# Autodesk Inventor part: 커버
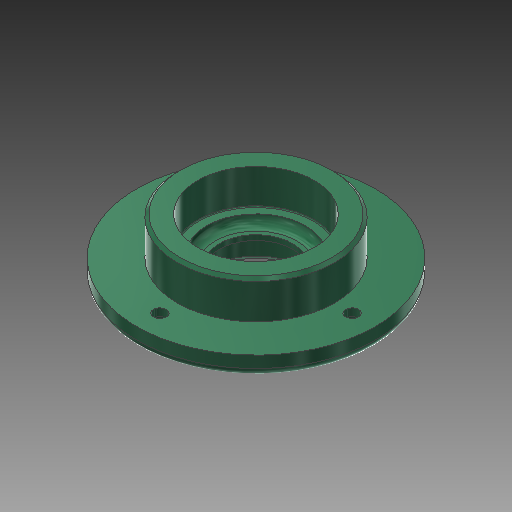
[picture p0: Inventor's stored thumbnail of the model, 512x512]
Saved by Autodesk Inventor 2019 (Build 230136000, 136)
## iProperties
Company: 한국ATC센터
Created: 2014-10
Part Number: 커버
Document SubType Name: Modeling
Designer: KYOUNG IL JANG
Density: 2.71 g/cm^3
Mass: 121.214 g
Surface Area: 161.165 cm^2
Volume: 44.7286 cm^3
Material: 알루미늄 6061
Appearance: 알루미늄 - 평지
Author: KYOUNG IL JANG
Revision Number: 1
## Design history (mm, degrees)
sketch "스케치1"
  geometry: C1 r 41 at (0, 0); 1 further point
  constraints: 1 centre point, 1 coincident
  dimensions: "d0" = 82 diameter of C1
extrude "돌출1" new body sketch "스케치1" distance "d1" = 7; taper "d2" = 0 deg
sketch "스케치2"
  geometry: C1 r 27 at (0, 0); 1 further point
  constraints: 1 centre point, 1 coincident
  dimensions: "d3" = 54 diameter of C1
extrude "돌출2" join sketch "스케치2" distance "d4" = 13; taper "d5" = 0 deg
sketch "스케치3"
  geometry: C1 r 20 at (0, 0); 1 further point
  constraints: 1 centre point, 1 coincident
  dimensions: "d6" = 40 diameter of C1
extrude "돌출3" join sketch "스케치3" distance "d7" = 5; taper "d8" = 0 deg
hole "구멍1" diameter "d11" = 25; stored, may be unused: countersink angle "d15" = 90 deg, drill point angle "d17" = 118 deg; dims "d9" = 10, "d10" = 10, "d12" = 6, "d13" = 32, "d14" = 8.3, "d16" = 8
hole "구멍2" diameter "d20" = 34; stored, may be unused: countersink angle "d24" = 90 deg, drill point angle "d26" = 0 deg; dims "d18" = 10, "d19" = 10, "d21" = 6, "d22" = 40, "d23" = 12, "d25" = 3
fillet "모깎기2" dims "d34" = 3
fillet "모깎기1" dims "d27" = 0.3
chamfer "모따기1" distance "d28" = 1; stored, may be unused: second distance "d29" = 2, angle "d30" = 45 deg
chamfer "모따기2" distance "d31" = 1.2; stored, may be unused: second distance "d32" = 2, angle "d33" = 30 deg
sketch "스케치4" dims "d35" = 66
  geometry: 3 further points
  constraints: 2 horizontal alignment, 1 coincident, 2 other
hole "구멍3" sketch "스케치4" at (33, 0) diameter "d36" = 4.5; stored, may be unused: countersink angle "d40" = 90 deg, drill point angle "d42" = 118 deg; dims "d37" = 6, "d38" = 8, "d39" = 4.4, "d41" = 13
node "솔리드1"
pattern_circular "원형 패턴1" dims angle "d44" = 360 deg
